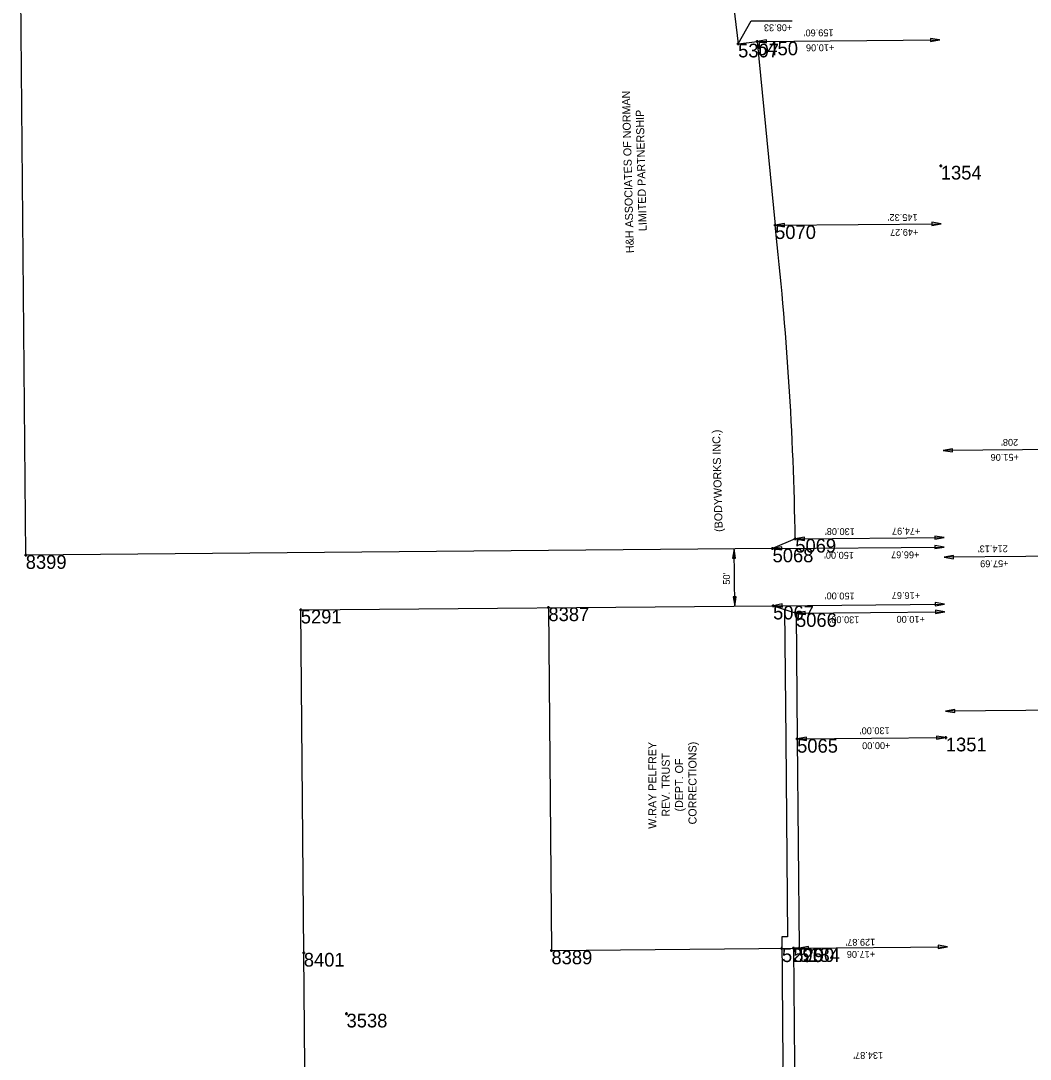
# Model space of a CAD drawing. Extents: x 2145146 to 2158053, y 137507 to 150829.
# Drawn here: x 2150029 to 2150911, y 141238 to 142146 of the extents above; entities that cross this region are included whole.
import ezdxf

# ---------------------------------------------------------------- set-up
doc = ezdxf.new("R2010")
doc.units = 0
for name, color, linetype in [('ALIGN_Cogo Points', 7, 'Continuous'), ('ALIGN_ROW Dimension', 7, 'Continuous'), ('ALIGN_ROW Line', 7, 'Continuous'), ('PLSS_Easement', 7, 'Continuous'), ('PLSS_Property Line', 7, 'Continuous'), ('PLSS_Text_TURNED OFF', 7, 'Continuous')]:
    doc.layers.add(name, color=color, linetype=linetype)

# ---------------------------------------------------------------- blocks, each defined once
blk = doc.blocks.new('Arrowhd')
at = {"layer": 'PLSS_Property Line'}
blk.add_lwpolyline([(0.125, -0.021), (0.125, 0.021), (0, 0)], close=True, dxfattribs=at)

msp = doc.modelspace()

# ---------------------------------------------------------------- linework, layer by layer
at = {"layer": 'ALIGN_Cogo Points'}
for points in [[(2150656.03, 142126.03), (2150656.03, 142127.23), (2150656.03, 142126.03), (2150654.83, 142126.03), (2150656.03, 142126.03), (2150656.03, 142124.83), (2150656.03, 142126.03), (2150657.23, 142126.03)], [(2150672.68, 142127.91), (2150672.68, 142129.11), (2150672.68, 142127.91), (2150671.48, 142127.91), (2150672.68, 142127.91), (2150672.68, 142126.71), (2150672.68, 142127.91), (2150673.88, 142127.91)], [(2150833.24, 142019.25), (2150833.24, 142020.45), (2150833.24, 142019.25), (2150832.04, 142019.25), (2150833.24, 142019.25), (2150833.24, 142018.05), (2150833.24, 142019.25), (2150834.44, 142019.25)], [(2150688.37, 141967.25), (2150688.37, 141968.45), (2150688.37, 141967.25), (2150687.17, 141967.25), (2150688.37, 141967.25), (2150688.37, 141966.05), (2150688.37, 141967.25), (2150689.57, 141967.25)], [(2150706.01, 141693.09), (2150706.01, 141694.29), (2150706.01, 141693.09), (2150704.81, 141693.09), (2150706.01, 141693.09), (2150706.01, 141691.89), (2150706.01, 141693.09), (2150707.21, 141693.09)], [(2150033.29, 141678.82), (2150033.29, 141680.02), (2150033.29, 141678.82), (2150032.09, 141678.82), (2150033.29, 141678.82), (2150033.29, 141677.62), (2150033.29, 141678.82), (2150034.49, 141678.82)], [(2150686.16, 141684.61), (2150686.16, 141685.81), (2150686.16, 141684.61), (2150684.96, 141684.61), (2150686.16, 141684.61), (2150686.16, 141683.41), (2150686.16, 141684.61), (2150687.36, 141684.61)], [(2150490.21, 141633.14), (2150490.21, 141634.34), (2150490.21, 141633.14), (2150489.01, 141633.14), (2150490.21, 141633.14), (2150490.21, 141631.94), (2150490.21, 141633.14), (2150491.41, 141633.14)], [(2150686.6, 141634.62), (2150686.6, 141635.82), (2150686.6, 141634.62), (2150685.4, 141634.62), (2150686.6, 141634.62), (2150686.6, 141633.42), (2150686.6, 141634.62), (2150687.8, 141634.62)], [(2150273.72, 141631.09), (2150273.72, 141632.29), (2150273.72, 141631.09), (2150272.52, 141631.09), (2150273.72, 141631.09), (2150273.72, 141629.89), (2150273.72, 141631.09), (2150274.92, 141631.09)], [(2150706.66, 141628.13), (2150706.66, 141629.33), (2150706.66, 141628.13), (2150705.46, 141628.13), (2150706.66, 141628.13), (2150706.66, 141626.93), (2150706.66, 141628.13), (2150707.86, 141628.13)], [(2150707.62, 141518.13), (2150707.62, 141519.33), (2150707.62, 141518.13), (2150706.42, 141518.13), (2150707.62, 141518.13), (2150707.62, 141516.93), (2150707.62, 141518.13), (2150708.82, 141518.13)], [(2150837.61, 141519.27), (2150837.61, 141520.47), (2150837.61, 141519.27), (2150836.41, 141519.27), (2150837.61, 141519.27), (2150837.61, 141518.07), (2150837.61, 141519.27), (2150838.81, 141519.27)], [(2150492.86, 141333.15), (2150492.86, 141334.35), (2150492.86, 141333.15), (2150491.66, 141333.15), (2150492.86, 141333.15), (2150492.86, 141331.95), (2150492.86, 141333.15), (2150494.06, 141333.15)], [(2150694.35, 141335.06), (2150694.35, 141336.26), (2150694.35, 141335.06), (2150693.15, 141335.06), (2150694.35, 141335.06), (2150694.35, 141333.86), (2150694.35, 141335.06), (2150695.55, 141335.06)], [(2150704.35, 141335.15), (2150704.35, 141336.35), (2150704.35, 141335.15), (2150703.15, 141335.15), (2150704.35, 141335.15), (2150704.35, 141333.95), (2150704.35, 141335.15), (2150705.55, 141335.15)], [(2150709.35, 141335.2), (2150709.35, 141336.4), (2150709.35, 141335.2), (2150708.15, 141335.2), (2150709.35, 141335.2), (2150709.35, 141334), (2150709.35, 141335.2), (2150710.55, 141335.2)], [(2150276.37, 141331.1), (2150276.37, 141332.3), (2150276.37, 141331.1), (2150275.17, 141331.1), (2150276.37, 141331.1), (2150276.37, 141329.9), (2150276.37, 141331.1), (2150277.57, 141331.1)], [(2150313.73, 141277.91), (2150313.73, 141279.11), (2150313.73, 141277.91), (2150312.53, 141277.91), (2150313.73, 141277.91), (2150313.73, 141276.71), (2150313.73, 141277.91), (2150314.93, 141277.91)]]:
    msp.add_lwpolyline(points, dxfattribs=at)
at = {"layer": 'ALIGN_ROW Dimension'}
for points in [[(2150656.1, 142126.03), (2150667.37, 142145.98), (2150703.3, 142146.04)], [(2150672.67, 142127.89), (2150832.27, 142129.29)], [(2150688.37, 141967.25), (2150833.68, 141968.52)], [(2151043.41, 141772.14), (2150835.42, 141770.32)], [(2150705.94, 141693.06), (2150836.08, 141694.2)], [(2150653.14, 141634.34), (2150652.7, 141684.32)], [(2150686.16, 141684.61), (2150836.16, 141685.93)], [(2151050.36, 141678.83), (2150836.23, 141676.95)], [(2150686.6, 141634.62), (2150836.59, 141635.93)], [(2150706.66, 141628.13), (2150836.65, 141629.27)], [(2151082.77, 141544.53), (2150837.41, 141542.38)], [(2150707.61, 141518.13), (2150837.61, 141519.26)], [(2150709.34, 141335.19), (2150839.22, 141336.33)]]:
    msp.add_lwpolyline(points, dxfattribs=at)
at = {"layer": 'ALIGN_ROW Line'}
for points in [[(2150631.53, 142295.02), (2150631.53, 142295.02), (2150668.09, 142174.84), (2150650.4, 142174.68), (2150656.03, 142126.03), (2150672.68, 142127.91), (2150688.37, 141967.25)], [(2150706.01, 141693.09), (2150686.16, 141684.61), (2150033.29, 141678.82)], [(2150273.72, 141631.09), (2150686.6, 141634.62), (2150706.66, 141628.13), (2150707.62, 141518.13), (2150709.35, 141335.2), (2150704.35, 141335.15), (2150705.24, 141233.86), (2150693.6, 141035.03), (2150673.39, 140680.22), (2150658.77, 140421.03), (2150632.34, 140395.87), (2150465.99, 140394.26), (2150394.65, 140393.58), (2150194.75, 140391.64), (2150194.84, 140381.64)]]:
    msp.add_lwpolyline(points, dxfattribs=at)
msp.add_arc((2147849.59, 141646.93), 2856.79, 0.92584, 6.43789, dxfattribs=at)
at = {"layer": 'PLSS_Easement'}
msp.add_lwpolyline([(2150696.63, 141631.37), (2150697.62, 141518.05), (2150699.26, 141345.1), (2150694.26, 141345.05), (2150695.24, 141234.11), (2150683.62, 141035.61), (2150683.58, 141034.94)], dxfattribs=at)
at = {"layer": 'PLSS_Property Line'}
for points in [[(2150033.29, 141678.82), (2150028.96, 142168.8)], [(2150490.17, 141633.16), (2150492.86, 141333.15), (2150704.35, 141335.15)], [(2150389.01, 141032.16), (2150279.02, 141031.11), (2150276.37, 141331.1), (2150273.72, 141631.09)]]:
    msp.add_lwpolyline(points, dxfattribs=at)

# ---------------------------------------------------------------- block references
at = {"layer": 'ALIGN_ROW Dimension'}
for p, xscale, yscale, rotation in [((2150672.7, 142127.89), 65.00000000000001, 65, 0.7805293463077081), ((2150832.22, 142129.31), 65, 65, 180), ((2150688.38, 141967.25), 65.00000000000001, 65, 0.7805293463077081), ((2150833.62, 141968.55), 65, 65, 180), ((2150835.4, 141770.32), 65.00000000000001, 65, 0.7805293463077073), ((2150706, 141693.08), 65, 65.00000000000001, 0.4451922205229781), ((2150836.07, 141694.2), 65, 65, -179.23112075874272), ((2150836.1, 141685.95), 65, 65, 180), ((2150652.7, 141684.32), 65, 64.99999999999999, -91.83689220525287), ((2150686.18, 141684.6), 65.00000000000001, 65, 0.7805293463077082), ((2150836.23, 141676.95), 65.00000000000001, 65, 0.7805293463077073), ((2150653.14, 141634.34), 65, 64.99999999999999, 90.50853156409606), ((2150686.57, 141634.66), 65.00000000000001, 65, 0.7805293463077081), ((2150836.53, 141635.95), 65, 65, 180), ((2150706.67, 141628.12), 65.00000000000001, 65, 0.7805293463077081), ((2150836.59, 141629.29), 65, 65, 180), ((2150837.39, 141542.38), 65.00000000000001, 65, 0.7805293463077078), ((2150707.63, 141518.13), 65.00000000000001, 65, 0.7805293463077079), ((2150837.56, 141519.29), 65, 65, 180), ((2150709.36, 141335.2), 65.00000000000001, 65, 0.7805293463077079), ((2150839.16, 141336.35), 65, 65, 180)]:
    msp.add_blockref('Arrowhd', p, dxfattribs=dict(at, xscale=xscale, yscale=yscale, rotation=rotation))

# ---------------------------------------------------------------- texts
at = {"layer": 'ALIGN_Cogo Points'}
for s, p in [('5307', (2150656.03, 142114.03)), ('5450', (2150672.68, 142115.91)), ('1354', (2150833.24, 142007.25)), ('5070', (2150688.37, 141955.25)), ('5069', (2150706.01, 141681.09)), ('8399', (2150033.29, 141666.82)), ('5068', (2150686.16, 141672.61)), ('8387', (2150490.21, 141621.14)), ('5067', (2150686.6, 141622.62)), ('5291', (2150273.72, 141619.09)), ('5066', (2150706.66, 141616.13)), ('5065', (2150707.62, 141506.13)), ('1351', (2150837.61, 141507.27)), ('8389', (2150492.86, 141321.15)), ('5296', (2150694.35, 141323.06)), ('5290', (2150704.35, 141323.15)), ('5184', (2150709.35, 141323.2)), ('8401', (2150276.37, 141319.1)), ('3538', (2150313.73, 141265.91))]:
    msp.add_text(s, height=12, dxfattribs=at).set_placement(p)
at = {"layer": 'ALIGN_ROW Dimension'}
for s, rotation, p in [('+08.33', 180.3718, (2150703.35, 142143.05)), ("159.60'", 180.3718, (2150739.47, 142138.58)), ('+10.06', 180.3718, (2150740.11, 142125.53)), ("145.32'", 180.3718, (2150812.94, 141977.15)), ('+49.27', 180.3718, (2150813.58, 141964.1)), ("208'", 180.3718, (2150900.85, 141780.5)), ('+51.06', 180.3718, (2150901.49, 141767.45)), ("130.08'", 179.59675, (2150758.1, 141702.32)), ('+74.97', 179.59675, (2150815.34, 141702.66)), ("214.13'", 180.3718, (2150891.74, 141687.43)), ("150.00'", 179.59675, (2150757.32, 141681.64)), ('+66.67', 179.59675, (2150814.56, 141681.99)), ('+57.69', 180.3718, (2150892.39, 141674.38)), ("50'", 90.65899, (2150648.97, 141653.05)), ("150.00'", 179.59675, (2150757.91, 141646.04)), ('+16.67', 179.59675, (2150815.15, 141646.38)), ("130.00'", 179.59675, (2150762.07, 141625.27)), ('+10.00', 179.59675, (2150819.31, 141625.61)), ("130.00'", 180.3718, (2150788.53, 141528.39)), ('+00.00', 180.3718, (2150789.18, 141515.34)), ("129.87'", 180.3718, (2150775.92, 141343.41)), ('+17.06', 180.3718, (2150775.79, 141332.87)), ("134.87'", 180.3718, (2150782.79, 141244.5))]:
    msp.add_text(s, height=6, rotation=rotation, dxfattribs=at).set_placement(p)
at = {"layer": 'PLSS_Text_TURNED OFF'}
for s, rotation, p in [('H&H ASSOCIATES OF NORMAN', 91.42926, (2150564.94, 141943.02)), ('LIMITED PARTNERSHIP', 91.42926, (2150576.16, 141962.24)), ('(BODYWORKS INC.)', 91.42926, (2150642.56, 141699.24)), ('W.RAY PELFREY', 90, (2150584.59, 141439.58)), ('CORRECTIONS)', 90, (2150619.66, 141443.39)), ('REV. TRUST', 90, (2150596.28, 141450.19)), ('(DEPT. OF', 90, (2150607.97, 141454.69))]:
    msp.add_text(s, height=7, rotation=rotation, dxfattribs=at).set_placement(p)

doc.saveas('drawing.dxf')
